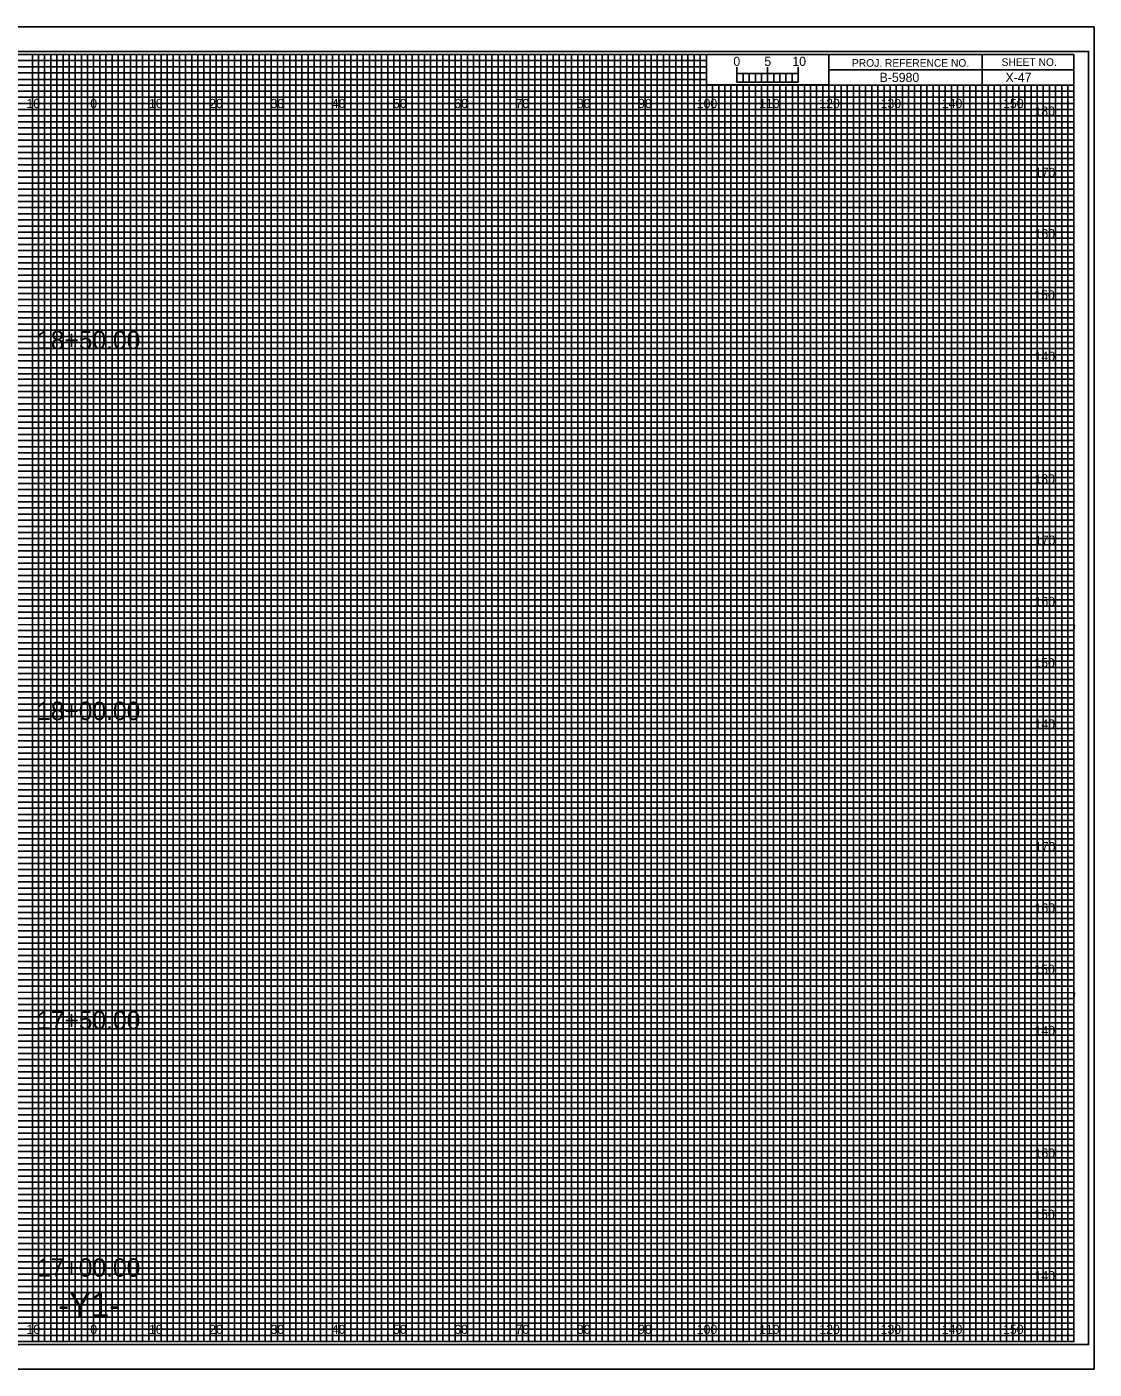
# Model space of a CAD drawing. Extents: x -13 to 323, y -5 to 4834.
# Drawn here: x 149.1 to 323.3, y 215.5 to 434.5 of the extents above; entities that cross this region are included whole.
import ezdxf

# ---------------------------------------------------------------- set-up
doc = ezdxf.new("R2010")
doc.units = 0
for name, color, linetype in [('Exist CMT Pavement', 7, 'Continuous'), ('Exist Cross Section Cell', 7, 'Continuous'), ('Exist XS Center Line Elevation Label', 7, 'Continuous'), ('Exist XS Ground Line', 7, 'Continuous'), ('Prop CMT Pvmt Course 1', 7, 'Continuous'), ('Prop CMT Pvmt Course 1 Wedge', 7, 'Continuous'), ('Prop CMT Pvmt Course 2', 7, 'Continuous'), ('Prop CMT Pvmt Course 2 Wedge', 7, 'Continuous'), ('Prop CMT Pvmt Course 3', 7, 'Continuous'), ('Prop CMT Pvmt Course 3 Wedge', 7, 'Continuous'), ('Prop CMT Pvmt Surface', 7, 'Continuous'), ('Prop CMT Pvmt Surface Shoulder', 7, 'Continuous'), ('Prop CMT Shld Paved Course 1', 7, 'Continuous'), ('Prop CMT Shld Paved Course 2', 7, 'Continuous'), ('Prop CMT Shld Paved Course 3', 7, 'Continuous'), ('Prop CMT Slope Grass', 7, 'Continuous'), ('Prop CMT Subgrade Earthwork', 7, 'Continuous')]:
    doc.layers.add(name, color=color, linetype=linetype)

msp = doc.modelspace()

# ---------------------------------------------------------------- linework, layer by layer
at = {"layer": 'Exist XS Center Line Elevation Label'}
for points in [[(145, 220), (155, 220), (155, 430), (165, 430), (165, 220), (175, 220), (175, 430), (185, 430), (185, 220), (195, 220), (195, 430), (205, 430), (205, 220), (215, 220), (215, 430), (225, 430), (225, 220), (235, 220), (235, 430), (245, 430), (245, 220), (255, 220), (255, 430), (259.93, 430), (260, 430), (260, 425), (264.99, 425), (264.99, 220), (275, 220), (275, 425), (285, 425), (285, 220), (295, 220), (295, 425), (305, 425), (305, 220), (315, 220), (315, 425)], [(0, 425), (275, 425)], [(0, 405), (320, 405), (320, 415), (0, 415)], [(0, 385), (320, 385), (320, 395), (0, 395)], [(0, 365), (320, 365), (320, 375), (0, 375)], [(0, 345), (320, 345), (320, 355), (0, 355)], [(0, 325), (320, 325), (320, 335), (0, 335)], [(0, 305), (320, 305), (320, 315), (0, 315)], [(0, 285), (320, 285), (320, 295), (0, 295)], [(0, 265), (320, 265), (320, 275), (0, 275)], [(0, 245), (320, 245), (320, 255), (0, 255)], [(0, 225), (320, 225), (320, 235), (0, 235)]]:
    msp.add_lwpolyline(points, dxfattribs=at)
at = {"layer": 'Exist XS Ground Line'}
for p, q in [((150, 430), (140, 430)), ((150, 220), (150, 430)), ((170, 430), (160, 430)), ((160, 430), (160, 220)), ((170, 220), (170, 430)), ((190, 430), (180, 430)), ((180, 430), (180, 220)), ((190, 220), (190, 430)), ((210, 430), (200, 430)), ((200, 430), (200, 220)), ((210, 220), (210, 430)), ((230, 430), (220, 430)), ((220, 430), (220, 220)), ((230, 220), (230, 430)), ((250, 430), (240, 430)), ((240, 430), (240, 220)), ((250, 220), (250, 430)), ((260, 430), (260, 220)), ((270, 220), (270, 425)), ((290, 425), (280, 425)), ((280, 425), (280, 220)), ((290, 220), (290, 425)), ((310, 425), (300, 425)), ((300, 425), (300, 220)), ((310, 220), (310, 425)), ((160, 220), (150, 220)), ((180, 220), (170, 220)), ((200, 220), (190, 220)), ((220, 220), (210, 220)), ((240, 220), (230, 220)), ((260, 220), (250, 220)), ((280, 220), (270, 220)), ((300, 220), (290, 220)), ((320, 220), (310, 220)), ((320, 220), (320, 220))]:
    msp.add_line(p, q, dxfattribs=at)
for points in [[(0, 420), (320, 420), (320, 410), (0, 410)], [(0, 400), (320, 400), (320, 390), (0, 390)], [(0, 380), (320, 380), (320, 370), (0, 370)], [(0, 360), (320, 360), (320, 350), (0, 350)], [(0, 340), (320, 340), (320, 330), (0, 330)], [(0, 320), (320, 320), (320, 310), (0, 310)], [(0, 300), (320, 300), (320, 290), (0, 290)], [(0, 280), (320, 280), (320, 270), (0, 270)], [(0, 260), (320, 260), (320, 250), (0, 250)], [(0, 240), (320, 240), (320, 230), (0, 230)]]:
    msp.add_lwpolyline(points, dxfattribs=at)
at = {"layer": 'Prop CMT Pvmt Course 1'}
for p, q in [((267, 425), (266.01, 425)), ((266.01, 425), (266.01, 220)), ((267, 220), (267, 425)), ((269, 425), (268, 425)), ((268, 425), (268, 220)), ((269, 220), (269, 425)), ((266.01, 220), (265, 220)), ((268, 220), (267, 220))]:
    msp.add_line(p, q, dxfattribs=at)
for points in [[(150, 220), (151, 220), (151, 430), (152, 430), (152, 220)], [(152, 220), (153, 220), (153, 430), (154, 430), (154, 220)], [(155, 220), (156, 220), (156, 430), (157, 430), (157, 220)], [(157, 220), (158, 220), (158, 430), (159, 430), (159, 220)], [(160, 220), (161, 220), (161, 430), (162, 430), (162, 220)], [(162, 220), (163, 220), (163, 430), (164, 430), (164, 220)], [(165, 220), (166, 220), (166, 430), (167, 430), (167, 220)], [(167, 220), (168, 220), (168, 430), (169, 430), (169, 220)], [(170, 220), (171, 220), (171, 430), (172, 430), (172, 220)], [(172, 220), (173, 220), (173, 430), (174, 430), (174, 220)], [(175, 220), (176, 220), (176, 430), (177, 430), (177, 220)], [(177, 220), (178, 220), (178, 430), (179, 430), (179, 220)], [(180, 220), (181, 220), (181, 430), (182, 430), (182, 220)], [(182, 220), (183, 220), (183, 430), (184, 430), (184, 220)], [(185, 220), (186, 220), (186, 430), (187, 430), (187, 220)], [(187, 220), (188, 220), (188, 430), (189, 430), (189, 220)], [(190, 220), (191, 220), (191, 430), (192, 430), (192, 220)], [(192, 220), (193, 220), (193, 430), (194, 430), (194, 220)], [(195, 220), (196, 220), (196, 430), (197, 430), (197, 220)], [(197, 220), (198, 220), (198, 430), (199, 430), (199, 220)], [(200, 220), (201, 220), (201, 430), (202, 430), (202, 220)], [(202, 220), (203, 220), (203, 430), (204, 430), (204, 220)], [(205, 220), (206, 220), (206, 430), (207, 430), (207, 220)], [(207, 220), (208, 220), (208, 430), (209, 430), (209, 220)], [(210, 220), (211, 220), (211, 430), (212, 430), (212, 220)], [(212, 220), (213, 220), (213, 430), (214, 430), (214, 220)], [(215, 220), (216, 220), (216, 430), (217, 430), (217, 220)], [(217, 220), (218, 220), (218, 430), (219, 430), (219, 220)], [(220, 220), (221, 220), (221, 430), (222, 430), (222, 220)], [(222, 220), (223, 220), (223, 430), (224, 430), (224, 220)], [(225, 220), (226, 220), (226, 430), (227, 430), (227, 220)], [(227, 220), (228, 220), (228, 430), (229, 430), (229, 220)], [(230, 220), (231, 220), (231, 430), (232, 430), (232, 220)], [(232, 220), (233, 220), (233, 430), (234, 430), (234, 220)], [(235, 220), (236, 220), (236, 430), (237, 430), (237, 220)], [(237, 220), (238, 220), (238, 430), (239, 430), (239, 220)], [(240, 220), (241, 220), (241, 430), (242, 430), (242, 220)], [(242, 220), (243, 220), (243, 430), (244, 430), (244, 220)], [(245, 220), (246, 220), (246, 430), (247, 430), (247, 220)], [(247, 220), (248, 220), (248, 430), (249, 430), (249, 220)], [(250, 220), (251, 220), (251, 430), (252, 430), (252, 220)], [(252, 220), (253, 220), (253, 430), (254, 430), (254, 220)], [(255, 220), (256, 220), (256, 430), (257, 430), (257, 220)], [(257, 220), (258, 220), (258, 430), (259, 430), (259, 220)], [(260, 220), (261, 220), (261, 425), (262.02, 425), (262.02, 220)], [(262, 220), (263, 220), (263, 425), (263.99, 425), (263.99, 220)], [(270, 220), (270.98, 220), (270.98, 425), (272, 425), (272, 220)], [(272, 220), (273, 220), (273, 425), (274.05, 425), (274.05, 220)], [(275, 220), (276, 220), (276, 425), (277, 425), (277, 220)], [(277, 220), (278, 220), (278, 425), (279, 425), (279, 220)], [(280, 220), (281, 220), (281, 425), (282, 425), (282, 220)], [(282, 220), (283, 220), (283, 425), (284, 425), (284, 220)], [(285, 220), (286, 220), (286, 425), (287, 425), (287, 220)], [(287, 220), (288, 220), (288, 425), (289, 425), (289, 220)], [(290, 220), (291, 220), (291, 425), (292, 425), (292, 220)], [(292, 220), (293, 220), (293, 425), (294, 425), (294, 220)], [(295, 220), (296, 220), (296, 425), (297, 425), (297, 220)], [(297, 220), (298, 220), (298, 425), (299, 425), (299, 220)], [(300, 220), (301, 220), (301, 425), (302, 425), (302, 220)], [(302, 220), (303, 220), (303, 425), (304, 425), (304, 220)], [(305, 220), (306, 220), (306, 425), (307, 425), (307, 220)], [(307, 220), (308, 220), (308, 425), (309, 425), (309, 220)], [(310, 220), (311, 220), (311, 425), (312, 425), (312, 220)], [(312, 220), (313, 220), (313, 425), (314, 425), (314, 220)], [(315, 220), (316, 220), (316, 425), (317, 425), (317, 220)], [(317, 220), (318, 220), (318, 425), (319, 425), (319, 220)]]:
    msp.add_lwpolyline(points, dxfattribs=at)
at = {"layer": 'Prop CMT Pvmt Course 2'}
for p, q in [((323.3, 434.5), (-13.4, 434.5)), ((-13.4, 215.5), (323.3, 215.5))]:
    msp.add_line(p, q, dxfattribs=at)
at = {"layer": 'Prop CMT Pvmt Surface Shoulder'}
for p, q in [((305, 430), (305, 425)), ((305, 425), (305, 430)), ((280, 427.5), (280, 425)), ((320, 427.49), (280, 427.49)), ((280, 425), (320, 425))]:
    msp.add_line(p, q, dxfattribs=at)
for points in [[(320, 430), (0, 430), (0, 220), (320, 220)], [(280, 430), (260, 430), (260, 425.03), (280, 425.03)], [(320, 430), (280, 430), (280, 425), (320, 425)]]:
    msp.add_lwpolyline(points, close=True, dxfattribs=at)
at = {"layer": 'Prop CMT Shld Paved Course 1'}
msp.add_lwpolyline([(-13.4, 215.5), (323.3, 215.5), (323.3, 434.5), (-13.4, 434.5)], close=True, dxfattribs=at)
at = {"layer": 'Prop CMT Shld Paved Course 2'}
msp.add_lwpolyline([(-10.8, 219.5), (322.4, 219.5), (322.4, 430.5), (-10.8, 430.5)], close=True, dxfattribs=at)
at = {"layer": 'Prop CMT Shld Paved Course 3'}
for p, q in [((150, 220), (150, 430)), ((160, 220), (160, 430)), ((170, 220), (170, 430)), ((180, 220), (180, 430)), ((190, 220), (190, 430)), ((200, 220), (200, 430)), ((210, 220), (210, 430)), ((220, 220), (220, 430)), ((230, 220), (230, 430)), ((240, 220), (240, 430)), ((250, 220), (250, 430)), ((260, 220), (260, 424.69)), ((270, 220), (270, 424.69)), ((280, 220), (280, 424.69)), ((290, 220), (290, 424.69)), ((300, 220), (300, 424.69)), ((310, 220), (310, 424.69)), ((0, 420), (320, 420)), ((0, 410), (320, 410)), ((0, 400), (320, 400)), ((0, 390), (320, 390)), ((0, 380), (320, 380)), ((0, 370), (320, 370)), ((0, 360), (320, 360)), ((0, 350), (320, 350)), ((0, 340), (320, 340)), ((0, 330), (320, 330)), ((0, 320), (320, 320)), ((0, 310), (320, 310)), ((0, 300), (320, 300)), ((0, 290), (320, 290)), ((0, 280), (320, 280)), ((0, 270), (320, 270)), ((0, 260), (320, 260)), ((0, 250), (320, 250)), ((0, 240), (320, 240)), ((0, 230), (320, 230))]:
    msp.add_line(p, q, dxfattribs=at)
at = {"layer": 'Prop CMT Slope Grass'}
for p, q in [((0, 429), (260, 429)), ((260, 427.98), (0, 427.98)), ((260, 429), (260, 427.98)), ((0, 427), (260, 427)), ((260, 425.89), (0, 425.89)), ((260, 427), (260, 425.89)), ((0, 424), (320, 424))]:
    msp.add_line(p, q, dxfattribs=at)
for points in [[(0, 423), (270, 423), (320, 423), (320, 422), (0, 422)], [(0, 421), (320, 421), (320, 419), (0, 419)], [(0, 418), (320, 418), (320, 417), (0, 416.98)], [(0, 416), (320, 416), (320, 414), (0, 414)], [(0, 413), (320, 413), (320, 412), (0, 412)], [(0, 411), (320, 411), (320, 409), (0, 409)], [(0, 408), (320, 408), (320, 407), (0, 407)], [(0, 406), (320, 406), (320, 404), (0, 404)], [(0, 403), (320, 403), (320, 402), (0, 402)], [(0, 401), (320, 401), (320, 399), (0, 399)], [(0, 398), (320, 398), (320, 397), (0, 397)], [(0, 396), (320, 396), (320, 393.95), (320, 393), (320, 392), (0, 392)], [(0, 394), (320, 394), (320, 393), (0, 393)], [(0, 391), (320, 391), (320, 389), (0, 389.03)], [(0, 389.03), (320, 389), (320, 388), (0, 388)], [(0, 387), (320, 387), (320, 386), (0, 386)], [(0, 384), (320, 384), (320, 383), (0, 383)], [(0, 382), (320, 382), (320, 381), (0, 381)], [(-0.07, 378.89), (320, 378.89), (320, 377.88), (-0.07, 377.88)], [(0, 377), (320, 377), (320, 376), (0, 376)], [(0, 374), (320, 374), (320, 373), (0, 373)], [(0, 372), (320, 372), (320, 371), (0, 371)], [(0, 369), (320, 369), (320, 368), (0, 368)], [(0, 367), (320, 367), (320, 366), (0, 366)], [(0, 364), (320, 364), (320, 363), (0, 363)], [(0, 362), (320, 362), (320, 361), (0, 361)], [(0, 359), (320, 359), (319.99, 357.98), (0, 358)], [(0, 357), (320, 357), (320, 356), (0, 356)], [(0, 354), (320, 354), (320, 353), (0, 353)], [(0, 352), (320, 352), (320, 351), (0, 351)], [(0, 349), (320, 349), (320, 348), (0, 348)], [(0, 347), (320, 347), (320, 346), (0, 346)], [(0, 344), (320, 344), (320, 343), (0, 343)], [(0, 342), (320, 342), (320, 341), (0, 341)], [(0, 339), (320, 339), (320, 338), (0, 338)], [(0, 336.99), (320.07, 336.91), (320, 336), (0, 336)], [(0, 334), (320, 334), (320, 333), (0, 333)], [(0, 332), (320, 332), (320, 331), (0, 331)], [(0, 329), (320, 329), (320, 328), (0, 328)], [(0, 327), (320, 327), (320, 326), (0, 326)], [(0, 324), (320, 324), (320, 323), (0, 323)], [(0, 322), (320, 322), (320, 321), (0, 321)], [(0, 319), (320, 319), (320, 318), (0, 318)], [(0, 317), (320, 317), (320, 316), (0, 316)], [(0, 314), (320, 314), (320, 313), (0, 313)], [(0, 312), (320, 312), (320, 311), (0, 311)], [(0, 309), (320, 309), (320, 308), (0, 308)], [(0, 307), (320, 307), (320, 306), (0, 306)], [(0, 304), (320, 304), (320, 303), (0, 303)], [(0, 302), (320, 302), (320, 301), (0, 301)], [(0, 299), (320, 299), (319.99, 297.98), (0, 298)], [(0, 297), (320, 297), (320, 296), (0, 296)], [(0, 294), (320, 294), (320, 293), (0, 293)], [(0, 292), (320, 292), (320, 291), (0, 291)], [(0, 289), (320, 289), (320, 288), (0, 288)], [(0, 287), (320, 287), (320, 286), (0, 286)], [(0, 284), (320, 284), (320, 283), (0, 283)], [(0, 282), (320, 282), (320, 281), (0, 281)], [(0, 279), (320, 279), (320, 278), (0, 278)], [(0, 276.99), (320.07, 276.91), (320, 276), (0, 276)], [(0, 274), (320, 274), (320, 273), (0, 273)], [(0, 272), (320, 272), (320, 271), (0, 271)], [(0, 269), (320, 269), (320, 268), (0, 268)], [(0, 267), (320, 267), (320, 266), (0, 266)], [(0, 264), (320, 264), (320, 263), (0, 263)], [(0, 262), (320, 262), (320, 261), (0, 261)], [(0, 259), (320, 259), (320, 258), (0, 258)], [(0, 257), (320, 257), (320, 256), (0, 256)], [(0, 254), (320, 254), (320, 253), (0, 253)], [(0, 252), (320, 252), (320, 251), (0, 251)], [(0, 249), (320, 249), (320, 248), (0, 248)], [(0, 247), (320, 247), (320, 246), (0, 246)], [(0, 244), (320, 244), (320, 243), (0, 243)], [(0, 242), (320, 242), (320, 241), (0, 241)], [(0, 239), (320, 239), (320, 238), (0, 238)], [(0, 237), (320, 237), (320, 236), (0, 236)], [(0, 234), (320, 234), (320, 233), (0, 233)], [(0, 232), (320, 232), (320, 231), (0, 231)], [(0, 229), (320, 229), (320, 228), (0, 228)], [(0, 227), (320, 227), (320, 226), (0, 226)], [(0, 224), (320, 224), (320, 223), (0, 223)], [(0, 222), (320, 222), (320, 221), (0, 221)]]:
    msp.add_lwpolyline(points, dxfattribs=at)
at = {"layer": 'Prop CMT Subgrade Earthwork'}
for p, q in [((265, 425.49), (265, 427.9)), ((265, 426.9), (265, 427.9)), ((270, 425.49), (270, 427.9)), ((275, 425.49), (275, 427.9)), ((275, 426.9), (275, 427.9))]:
    msp.add_line(p, q, dxfattribs=at)
for points in [[(275, 426.9), (265, 426.9), (265, 425.49), (275, 425.49)], [(265, 426.9), (266, 426.9), (266, 425.49), (265, 425.49)], [(267, 426.9), (268, 426.9), (268, 425.49), (267, 425.49)], [(269, 426.9), (270, 426.9), (270, 425.49), (269, 425.49)], [(271, 426.9), (272, 426.9), (272, 425.49), (271, 425.49)], [(273, 426.9), (274, 426.9), (274, 425.49), (273, 425.49)]]:
    msp.add_lwpolyline(points, close=True, dxfattribs=at)

# ---------------------------------------------------------------- texts
at = {"layer": 'Exist CMT Pavement'}
msp.add_text('-Y1-', height=4, dxfattribs=at).set_placement((154.21, 224))
at = {"layer": 'Exist Cross Section Cell'}
for s, p in [('10', (149.04, 421.25)), ('0', (159.45, 421.25)), ('0', (159.45, 421.25)), ('10', (169.04, 421.25)), ('20', (178.86, 421.25)), ('30', (188.86, 421.25)), ('40', (198.86, 421.25)), ('50', (208.86, 421.25)), ('60', (218.86, 421.25)), ('70', (228.86, 421.25)), ('80', (238.86, 421.25)), ('90', (248.86, 421.25)), ('100', (258.44, 421.25)), ('110', (268.62, 421.25)), ('120', (278.44, 421.25)), ('130', (288.44, 421.25)), ('140', (298.44, 421.25)), ('150', (308.44, 421.25)), ('10', (149.04, 221.25)), ('0', (159.45, 221.25)), ('0', (159.45, 221.25)), ('10', (169.04, 221.25)), ('20', (178.86, 221.25)), ('30', (188.86, 221.25)), ('40', (198.86, 221.25)), ('50', (208.86, 221.25)), ('60', (218.86, 221.25)), ('70', (228.86, 221.25)), ('80', (238.86, 221.25)), ('90', (248.86, 221.25)), ('100', (258.44, 221.25)), ('110', (268.62, 221.25)), ('120', (278.44, 221.25)), ('130', (288.44, 221.25)), ('140', (298.44, 221.25)), ('150', (308.44, 221.25))]:
    msp.add_text(s, height=1.5, dxfattribs=at).set_placement(p)
at = {"layer": 'Prop CMT Pvmt Course 1 Wedge'}
for s, p in [('18+50.00', (150.77, 381.9)), ('18+00.00', (150.77, 321.4)), ('17+50.00', (150.77, 270.94)), ('17+00.00', (150.77, 230.58))]:
    msp.add_text(s, height=3, dxfattribs=at).set_placement(p)
at = {"layer": 'Prop CMT Pvmt Course 2 Wedge'}
msp.add_text('X-47', height=1.5, dxfattribs=at).set_placement((308.83, 425.5))
at = {"layer": 'Prop CMT Pvmt Course 3'}
for s, p in [('180', (313.55, 420)), ('170', (313.61, 410)), ('160', (313.57, 400)), ('150', (313.52, 390)), ('140', (313.57, 380)), ('180', (313.55, 360)), ('170', (313.61, 350)), ('160', (313.57, 340)), ('150', (313.52, 330)), ('140', (313.57, 320)), ('170', (313.61, 300)), ('160', (313.57, 290)), ('150', (313.52, 280)), ('140', (313.57, 270)), ('160', (313.57, 250)), ('150', (313.52, 240)), ('140', (313.57, 230))]:
    msp.add_text(s, height=1.5, dxfattribs=at).set_placement(p)
at = {"layer": 'Prop CMT Pvmt Course 3 Wedge'}
msp.add_text('B-5980', height=1.5, dxfattribs=at).set_placement((288.28, 425.5))
at = {"layer": 'Prop CMT Pvmt Surface'}
for s, p in [('5', (269.47, 428.12)), ('10', (274.04, 428.12))]:
    msp.add_text(s, height=1.5, dxfattribs=at).set_placement(p)
at = {"layer": 'Prop CMT Pvmt Surface Shoulder'}
for s, p in [('PROJ. REFERENCE NO.', (283.77, 427.99)), ('SHEET NO.', (308.19, 428.12))]:
    msp.add_text(s, height=1.25, dxfattribs=at).set_placement(p)
at = {"layer": 'Prop CMT Subgrade Earthwork'}
msp.add_text('0', height=1.5, dxfattribs=at).set_placement((264.41, 428.12))

doc.saveas('drawing.dxf')
